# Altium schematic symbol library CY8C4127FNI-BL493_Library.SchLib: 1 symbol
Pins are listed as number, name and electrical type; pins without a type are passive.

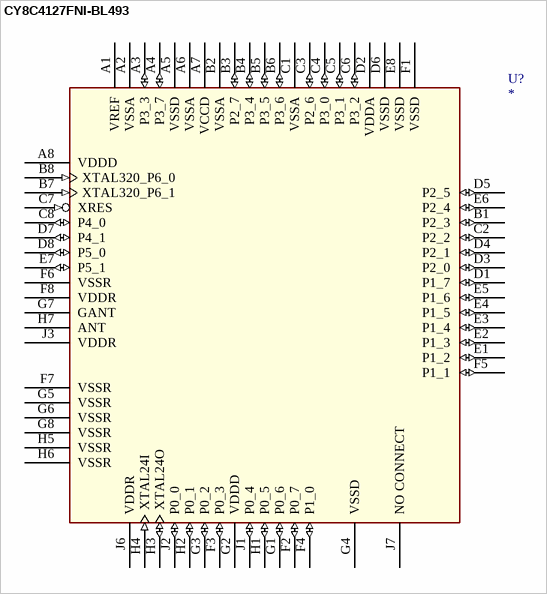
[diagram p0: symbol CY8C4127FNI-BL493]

## CY8C4127FNI-BL493
designator U?
footprint TBD
pins: A1 VREF (power), A2 VSSA (power), A3 P3_3 (io), A4 P3_7 (io), A5 VSSD (power), A6 VSSA (power), A7 VCCD (power), A8 VDDD (power), B1 P2_3 (io), B2 VSSA (power), B3 P2_7 (io), B4 P3_4 (io), B5 P3_5 (io), B6 P3_6 (io), B7 XTAL320_P6_1 (in), B8 XTAL320_P6_0 (in), C1 VSSA (power), C2 P2_2 (io), C3 P2_6 (io), C4 P3_0 (io), C5 P3_1 (io), C6 P3_2 (io), C7 XRES (in), C8 P4_0 (io), D1 P1_7 (io), D2 VDDA (power), D3 P2_0 (io), D4 P2_1 (io), D5 P2_5 (io), D6 VSSD (power), D7 P4_1 (io), D8 P5_0 (io), E1 P1_2 (io), E2 P1_3 (io), E3 P1_4 (io), E4 P1_5 (io), E5 P1_6 (io), E6 P2_4 (io), E7 P5_1 (io), E8 VSSD (power), F1 VSSD (power), F2 P0_7 (io), F3 P0_3 (io), F4 P1_0 (io), F5 P1_1 (io), F6 VSSR (power), F7 VSSR (power), F8 VDDR (power), G1 P0_6 (io), G2 VDDD (power), G3 P0_2 (io), G4 VSSD (power), G5 VSSR (power), G6 VSSR (power), G7 GANT (power), G8 VSSR (power), H1 P0_5 (io), H2 P0_1 (io), H3 XTAL24O (io), H4 XTAL24I (in), H5 VSSR (power), H6 VSSR (power), H7 ANT, J1 P0_4 (io), J2 P0_0 (io), J3 VDDR (power), J6 VDDR (power), J7 NO CONNECT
